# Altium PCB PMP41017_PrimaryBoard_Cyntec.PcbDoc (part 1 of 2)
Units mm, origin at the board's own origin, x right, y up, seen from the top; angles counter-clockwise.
Board outline 81.79 x 50.02 mm, 4 copper layers (Top Layer, Layer 2, Layer 3, Bottom Layer), stack 1.194 mm thick; 52 components, 42 nets, 218 pads, 652 vias.
Unrouted connection lines stored in the file: 2.
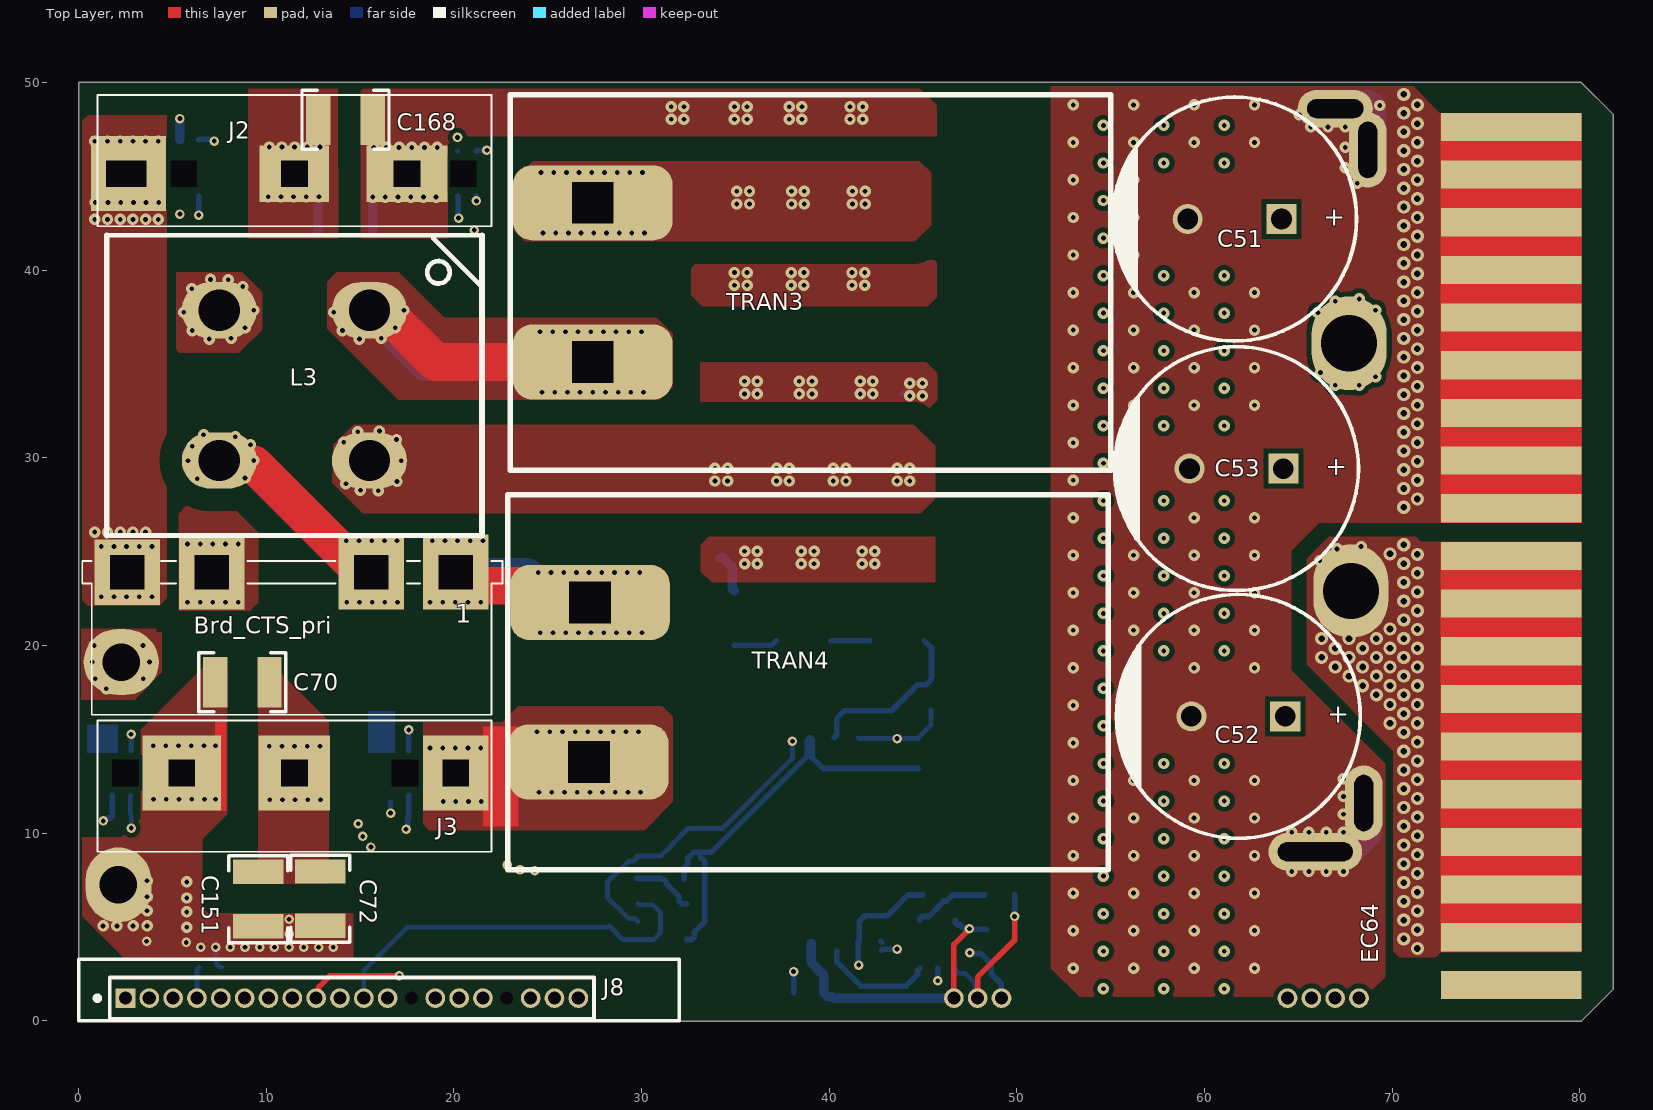
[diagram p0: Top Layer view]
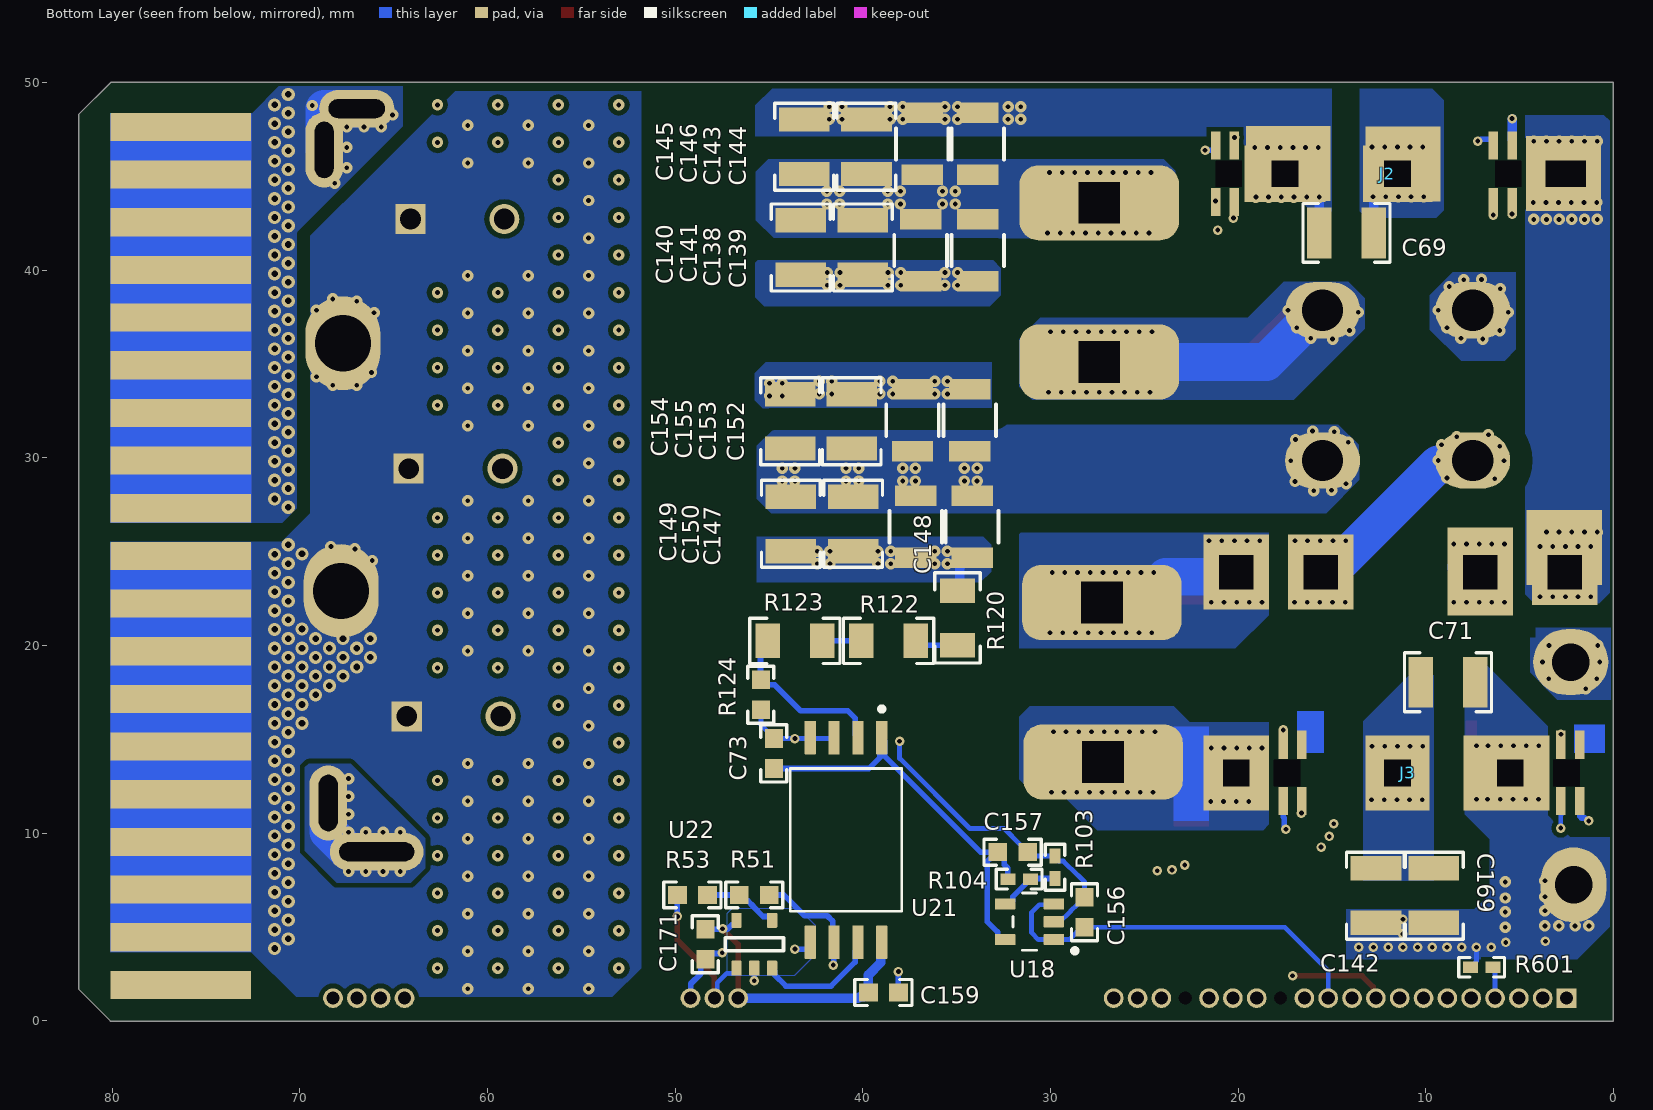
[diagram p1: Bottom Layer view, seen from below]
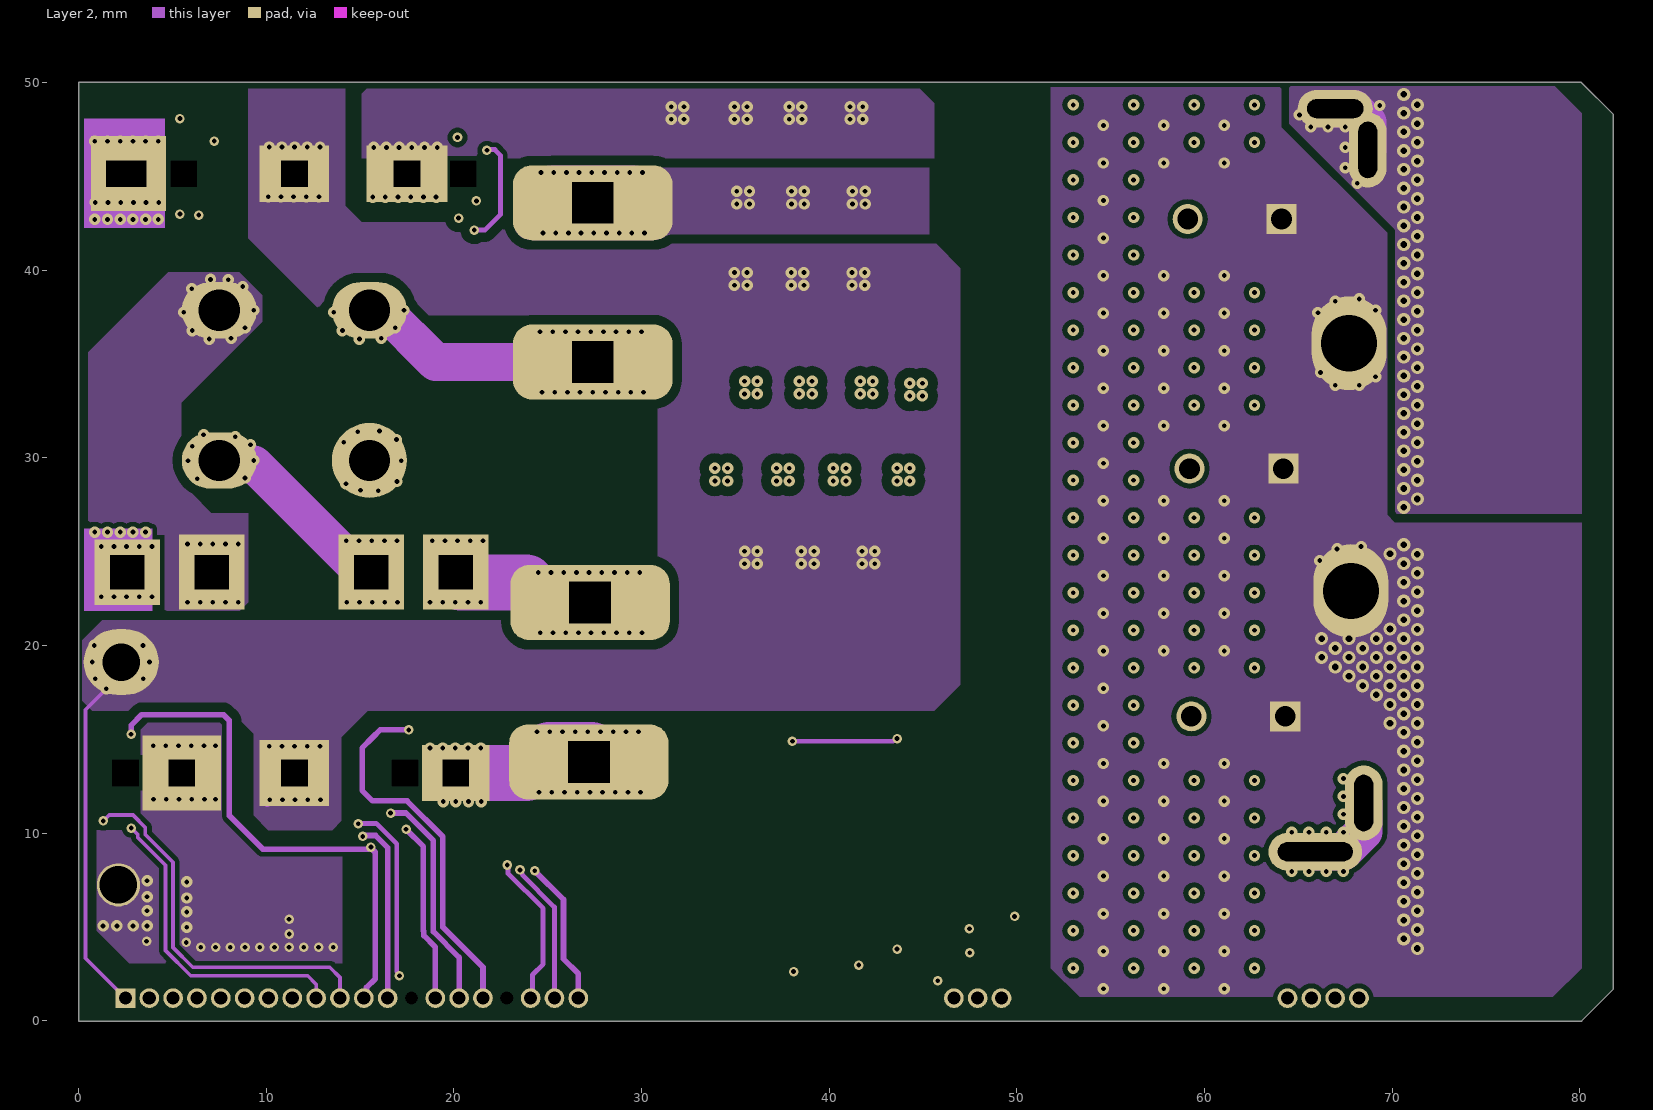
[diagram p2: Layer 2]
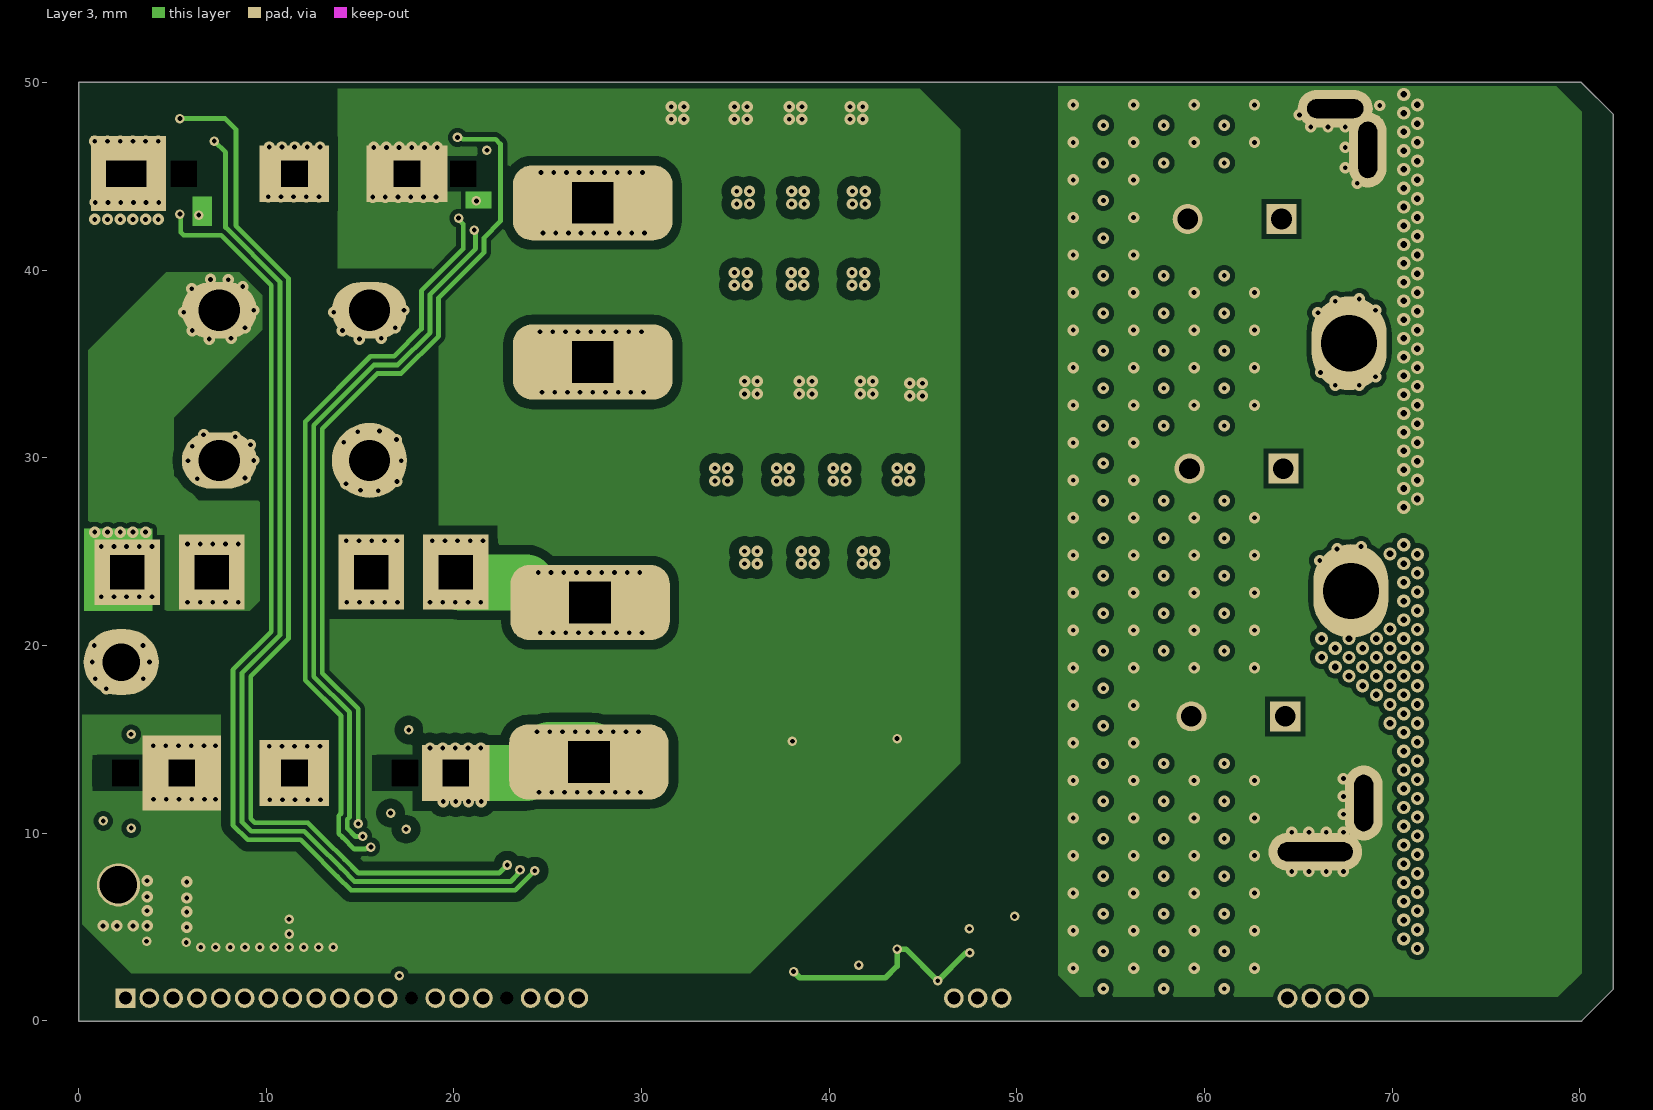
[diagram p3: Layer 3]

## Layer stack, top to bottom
Top Solder: solder mask 0.0102, Solder Resist, Dk 3.5
Top Layer: signal copper 0.07
Dielectric 1: prepreg 0.3048, PP-022, Dk 4.5
Layer 2: signal copper 0.07
Dielectric3: core 0.3048, Core-029, Dk 4.7
Layer 3: signal copper 0.07
Dielectric 5: prepreg 0.3048, PP-022, Dk 4.5
Bottom Layer: signal copper 0.07
Bottom Solder: solder mask 0.0102, Solder Resist, Dk 3.5

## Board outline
0,-0.017 0,50 70,50 80.071,50 81.788,48.283 81.788,1.683 80.088,-0.017

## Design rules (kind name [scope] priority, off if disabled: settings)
AcuteAngle [All] p1: minimum=4.50000000000000E+0001 checktracksonly=FALSE
AssemblyTestPointUsage [All] p1: valid=2
BoardOutlineClearance BoardOutlineClearance_MountingHoles [OnCopper and InComponentClass('Mounting Holes')] p1: gap=0.2 ignorepadtopadclearanceinfootprint=FALSE
BoardOutlineClearance BoardOutlineClearance_Poly [OnCopper and IsPoly] p2: gap=0.2 ignorepadtopadclearanceinfootprint=FALSE
BoardOutlineClearance [OnCopper and Not InComponentClass('Logo') and not InComponentClass('FiducialMark') and not InRegion(1000,500,4000,800) and not InPoly] p3: gap=0.2 ignorepadtopadclearanceinfootprint=FALSE
Clearance Clearance_HV [InNetClass('HV') And ( OnLayer('Top Layer') OR OnLayer('Bottom Layer')) vs InNetClass('All Nets')] p1: gap=1.2 ignorepadtopadclearanceinfootprint=TRUE
Clearance Clearance_HV_Mid [InNetClass('HV') And (OnMid OR OnMultiLayer) vs InNetClass('All Nets')] p2: gap=0.5 ignorepadtopadclearanceinfootprint=TRUE
Clearance Clearance_SW1P [InNetClass('SW1P') And ( OnLayer('Top Layer') OR OnLayer('Bottom Layer')) vs NOT InNetClass('SW1P')] p3: gap=1.2 ignorepadtopadclearanceinfootprint=TRUE
Clearance Clearance_SW1N [InNetClass('SW1N') And ( OnLayer('Top Layer') OR OnLayer('Bottom Layer')) vs NOT InNetClass('SW1N')] p4: gap=1.2 ignorepadtopadclearanceinfootprint=TRUE
Clearance Clearance_SW1N_Mid [InNetClass('SW1N') And ( OnMid OR OnMultiLayer) vs NOT InNetClass('SW1N')] p5: gap=0.5 ignorepadtopadclearanceinfootprint=TRUE
Clearance Clearance_SW2N_Mid [InNetClass('SW2N') And ( OnMid OR OnMultiLayer) vs NOT InNetClass('SW2N')] p6: gap=0.5 ignorepadtopadclearanceinfootprint=TRUE
Clearance Clearance_SW1P_Mid [InNetClass('SW1P') And ( OnMid OR OnMultiLayer) vs NOT InNetClass('SW1P')] p7: gap=0.5 ignorepadtopadclearanceinfootprint=TRUE
Clearance Clearance_SW2P_Mid [InNetClass('SW2P') And ( OnMid OR OnMultiLayer) vs NOT InNetClass('SW2p')] p8: gap=0.5 ignorepadtopadclearanceinfootprint=TRUE
Clearance Clearance_SW2P [InNetClass('SW2P') And ( OnLayer('Top Layer') OR OnLayer('Bottom Layer')) vs NOT InNetClass('SW2P')] p9: gap=1.2 ignorepadtopadclearanceinfootprint=TRUE
Clearance Clearance_SW2N [InNetClass('SW2N') And ( OnLayer('Top Layer') OR OnLayer('Bottom Layer')) vs NOT InNetClass('SW2N')] p10: gap=1.2 ignorepadtopadclearanceinfootprint=TRUE
Clearance Clearance_Keepouts [((IsTrack Or IsArc) And Not InPoly) And IsFree and IsKeepOut vs ((IsTrack Or IsArc) And Not InPoly) And IsFree and IsKeepOut] p11: gap=0 ignorepadtopadclearanceinfootprint=FALSE
Clearance Clearance_Poly [InPolygon] p12: gap=0.254 ignorepadtopadclearanceinfootprint=TRUE
Clearance Clearance_FiducialMark [IsKeepOut and InComponentClass('FiducialMark') vs IsPad and InComponentClass('FiducialMark')] p13: gap=0 ignorepadtopadclearanceinfootprint=FALSE
Clearance [All] p14: gap=0.203 ignorepadtopadclearanceinfootprint=TRUE
ComponentClearance ComponentClearance_MountingHoles_FiducialMarks [InComponentClass('Mounting Holes') vs InComponentClass('FiducialMark')] p1 off: gap=1.27 collisioncheckmode=3 verticalgap=0.254 showdistances=FALSE
ComponentClearance ComponentClearance_Shunt [InComponentClass('Header') vs InComponentClass('Shunt')] p2 off: gap=0 collisioncheckmode=3 verticalgap=0 showdistances=FALSE
ComponentClearance ComponentClearance_Logo [InComponentClass('Logo')] p3 off: gap=0.762 collisioncheckmode=3 verticalgap=0.254 showdistances=FALSE
ComponentClearance ComponentClearance_ScrewToNut [(HasFootprint('NY PMS 440 0025 PH')) vs (HasFootprint('Keystone_1902C'))] p4 off: gap=0.127 collisioncheckmode=3 verticalgap=0.254 showdistances=FALSE
ComponentClearance ComponentClearance_MountingHoles [InComponentClass('Mounting Holes')] p5 off: gap=2.54 collisioncheckmode=3 verticalgap=2540 showdistances=FALSE
ComponentClearance ComponentClearance_SmallPassives [HasFootprint('0201*') or HasFootprint('0402*') or HasFootprint('0508') or HasFootprint('0603*') or HasFootprint('0612') or HasFootprint('0805*') or HasFootprint('0815*') or HasFootprint('0830*') or HasFootprint('1206*') or HasFootprint('1210*') or HasFootprint('1808*') or HasFootprint('1812*') or HasFootprint('1825*') or HasFootprint('2010*') or HasFootprint('2220*') or HasFootprint('2225*') or HasFootprint('2512*') or HasFootprint('2728*') or HasFootprint('3518*') vs HasFootprint('0201*') or HasFootprint('0402*') or HasFootprint('0508') or HasFootprint('0603*') or HasFootprint('0612') or HasFootprint('0805*') or HasFootprint('0815*') or HasFootprint('0830*') or HasFootprint('1206*') or HasFootprint('1210*') or HasFootprint('1808*') or HasFootprint('1812*') or HasFootprint('1825*') or HasFootprint('2010*') or HasFootprint('2220*') or HasFootprint('2225*') or HasFootprint('2512*') or HasFootprint('2728*') or HasFootprint('3518*')] p6 off: gap=0.38 collisioncheckmode=3 verticalgap=0.254 showdistances=FALSE
ComponentClearance ComponentClearance_THtoSMT [IsThruComponent vs IsSMTComponent] p7 off: gap=0.762 collisioncheckmode=3 verticalgap=0.762 showdistances=FALSE
ComponentClearance ComponentClearance_THtoTH [IsThruComponent vs IsThruComponent] p8 off: gap=0.508 collisioncheckmode=3 verticalgap=0.762 showdistances=FALSE
ComponentClearance [All] p9 off: gap=0.508 collisioncheckmode=3 verticalgap=0.254 showdistances=FALSE
DiffPairsRouting [All] p1: maxlimit=2.54 minlimit=0.254 mostfreqgap=0.254 toplayer_minwidth=0.381 toplayer_maxwidth=0.381 toplayer_prefwidth=0.381 midlayer1_minwidth=0.381 midlayer1_maxwidth=0.381 midlayer1_prefwidth=0.381 midlayer2_minwidth=0.381 midlayer2_maxwidth=0.381 midlayer2_prefwidth=0.381 bottomlayer_minwidth=0.381 bottomlayer_maxwidth=0.381 bottomlayer_prefwidth=0.381 maxuncoupledlength=25.4
FabricationTestPointUsage TestPointUsage [All] p1: valid=2 allowmultiple=FALSE
FabricationTestpoint Testpoint [All] p1: side=3 testpointundercomponent=TRUE minsize=1.016 maxsize=2.54 preferedsize=1.524 minholesize=0 maxholesize=1.016 preferedholesize=0.813 testpointgrid=0.025 allowsidetop=TRUE allowsidebottom=TRUE usegrid=TRUE gridtolerance=0
FanoutControl Fanout_LCC [IsLCC] p1: bgadir=Out bgaviamode=Centered fanoutstyle=Auto fanoutdirection=Alternating viagrid=0.025 // Fanout_LCC (Default Rule)
FanoutControl Fanout_BGA [IsBGA] p2: bgadir=Out bgaviamode=Centered fanoutstyle=Auto fanoutdirection=Alternating viagrid=0.025 // Fanout_BGA (Default Rule)
FanoutControl Fanout_Default [All] p4: bgadir=Out bgaviamode=Centered fanoutstyle=Auto fanoutdirection=Alternating viagrid=0.025 // Fanout_Default (Default Rule)
FanoutControl Fanout_Small [(CompPinCount < 5)] p5: bgadir=Out bgaviamode=Centered fanoutstyle=Auto fanoutdirection=OutThenIn viagrid=0.025 // Fanout_Small (Default Rule)
Height [All] p1 off: minheight=0 maxheight=30 prefheight=12.7
HoleSize [All] p1: absolutevalues=TRUE maxlimit=6.375 minlimit=0.178 maxpercent=80.000 minpercent=20.000
MinimumAnnularRing MinimumAnnularRing_ThermalPadVias [IsVia and InAnyComponent] p1: minimumring=0.15
MinimumAnnularRing [All] p2: minimumring=0.12
MinimumSolderMaskSliver MinimumSolderMaskSliver_Logo [InComponentClass('Logo') vs InComponentClass('Logo')] p1: minsoldermaskwidth=0.018
MinimumSolderMaskSliver [All] p2: minsoldermaskwidth=0.1
PlaneConnect [All] p1: planeconnectstyle=Relief reliefexpansion=0.254 reliefentries=4 reliefconductorwidth=0.254 reliefairgap=0.254
PolygonConnect [All] p1: connectstyle=Direct reliefconductorwidth=0.254 reliefentries=4 polygonreliefangle="90 Angle" airgapwidth=0.254
RoutingVias ThermalPadVias [IsVia and InAnyComponent] p1: holewidth=0.2 width=0.5 viastyle="Through Hole" minholewidth=0.2 minwidth=0.5 maxholewidth=0.33 maxwidth=0.6
RoutingVias [All] p2: holewidth=0.3 width=0.5 viastyle="Through Hole" minholewidth=0.2 minwidth=0.5 maxholewidth=1.016 maxwidth=1.651
SilkToBoardRegionClearance [Not ((IsComment or IsDesignator) And (Hide <> 'False')) and not InRegion(1000,500,4000,800)] p1:
SilkToSilkClearance SilkToSilkClearance_Pb-FreeLogo [(HasFootprint('Pb-Free_Overlay_Medium') OR HasFootprint('Pb-Free_Overlay_Small')) vs (HasFootprint('Pb-Free_Overlay_Medium') OR HasFootprint('Pb-Free_Overlay_Small'))] p1: silktosilkclearance=0
SilkToSilkClearance [All] p2: silktosilkclearance=0.1
SilkToSolderMaskClearance SilkToComponentPadClearance [(IsPad or IsFill or IsRegion) and InAnycomponent] p1: minsilkscreentomaskgap=0.127 clearancetoexposedcopper=TRUE
SilkToSolderMaskClearance "Silk to Solder Mask Opening" [All] p2: minsilkscreentomaskgap=0.1 clearancetoexposedcopper=FALSE
SolderMaskExpansion [All] p1: expansion=0.05 istentingtop=FALSE
UnRoutedNet [All] p1: checkbadconnections=TRUE
Width [All] p1: maxlimit=5 minlimit=0.152 preferedwidth=0.254 checkconnectedcopper=TRUE
13 further rules are at their usual default settings.

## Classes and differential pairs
net class SW2P: GaN2_12V_H GaN2_INH GaN2_SW GaN2_SW_D TEMP_2H_1
net class SW2N: CT2_N CT2_P NetC147_2
net class SW1P: CT1_N CT1_P GaN1_12V_H GaN1_INH GAN1_SW1_D TEMP_1H_1 TR1_HV_P
net class SW1N: TR1_HV_N
net class HV: HVBUS

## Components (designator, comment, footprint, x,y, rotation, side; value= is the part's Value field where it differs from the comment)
Brd_CTS_pri "CTS daughter board" DB_PMP41017_CST 22.6,23.9 r180 top locked
C51 "860020378023" 860020378023 61.6,42.717 r180 top value=3300uF
C52 "860020378023" 860020378023 61.8,16.217 r180 top value=3300uF
C53 "860020378023" 860020378023 61.7,29.417 r180 top value=3300uF
C69 "CGA6L1X7T2J104K160AC" 1210_200 14.224,41.977 r0 bottom value=0.1uF
C70 "CGA6L1X7T2J104K160AC" 1210_200 8.724,18.034 r180 top value=0.1uF
C71 "CGA6L1X7T2J104K160AC" 1210_200 8.818,18.034 r180 bottom value=0.1uF
C72 "CGA6L1X7T2J104K160AC" 1210_200 12.88,6.5 r270 top value=0.1uF
C73 "GCM188R71E104KA57D" 0603 44.737,14.241 r90 bottom value=0.1uF
C138 "C3225C0G2J333J250AA" 1210_280 36.918,41.046 r90 bottom value=0.033uF
C139 "C3225C0G2J333J250AA" 1210_280 33.87,41.046 r90 bottom value=0.033uF
C140 "CGA6N4NP02J223J230AA" 1210_250 43.307,41.202 r90 bottom value=0.022uF
C141 "CGA6J4C0G2J103J125AA" 1210_150 39.994,41.202 r90 bottom value=0.01uF
C142 "CGA6L1X7T2J104K160AC" 1210_200 12.652,6.664 r270 bottom value=0.1uF
C143 "C3225C0G2J333J250AA" 1210_280 36.83,46.724 r90 bottom value=0.033uF
C144 "C3225C0G2J333J250AA" 1210_280 33.87,46.724 r90 bottom value=0.033uF
C145 "CGA6N4NP02J223J230AA" 1210_250 43.119,46.568 r90 bottom value=0.022uF
C146 "CGA6J4C0G2J103J125AA" 1210_150 39.805,46.568 r90 bottom value=0.01uF
C147 "C3225C0G2J333J250AA" 1210_280 37.173,26.32 r90 bottom value=0.033uF
C148 "C3225C0G2J333J250AA" 1210_280 34.173,26.32 r90 bottom value=0.033uF
C149 "CGA6N4NP02J223J230AA" 1210_250 43.83,26.475 r90 bottom value=0.022uF
C150 "CGA6J4C0G2J103J125AA" 1210_150 40.516,26.475 r90 bottom value=0.01uF
C151 "CGA6L1X7T2J104K160AC" 1210_200 9.578,6.477 r270 top value=0.1uF
C152 "C3225C0G2J333J250AA" 1210_280 34.304,31.996 r90 bottom value=0.033uF
C153 "C3225C0G2J333J250AA" 1210_280 37.354,31.996 r90 bottom value=0.033uF
C154 "CGA6N4NP02J223J230AA" 1210_250 43.873,31.941 r90 bottom value=0.022uF
C155 "CGA6J4C0G2J103J125AA" 1210_150 40.595,31.941 r90 bottom value=0.01uF
C156 "C1608X7R1E104K080AA" 0603 28.183,5.778 r90 bottom value=0.1uF
C157 "C1608X7R1E104K080AA" 0603 32.014,8.981 r180 bottom value=0.1uF
C159 "GCM188R71E104KA57D" 0603 38.901,1.501 r180 bottom value=0.1uF
C168 "CGA6L1X7T2J104K160AC" 1210_200 14.224,48.006 r0 top value=0.1uF
C169 "CGA6L1X7T2J104K160AC" 1210_200 9.578,6.664 r270 bottom value=0.1uF
C171 "GCM188R71E104KA57D" 0603 48.387,4.074 r270 bottom value=0.1uF
EC64 "EDGE_CONN_PCIe-x4" EC_10035388-102LF 81.788,47.625 r90 top
J2 "GaN Borad" ?#1 22,49.333 r180 top
J3 "GaN Borad" ?#2 1,9 r0 top
J8 "M52-5002045" M52-5002045 2.5,1.2 r0 top locked
L3 "PQ2016" "CHOKE-PQ2016 - H" 11.5,33.852 r180 top
R51 "RC0603FR-0712KL" 0603 45.781,6.701 r180 bottom value=12.0k
R53 "RC0603FR-0712KL" 0603 49.078,6.701 r180 bottom value=12.0k
R103 "" 0402 29.759,8.176 r270 bottom value=1.18Meg
R104 "" 0402 31.673,7.541 r0 bottom value=1.96Meg
R120 "CRCW12061M00FKEA" 1206 34.948,21.461 r90 bottom value=1.00Meg
R122 "CRCW12061M00FKEA" 1206 38.623,20.241 r180 bottom value=1.00Meg
R123 "CRCW12061M00FKEA" 1206 43.616,20.241 r180 bottom value=1.00Meg
R124 "RC0603FR-0712KL" 0603 45.429,17.37 r90 bottom value=12.0k
R601 "" 0402 7.024,2.846 r180 bottom value=0
TRAN3 "PQ32" PQ3220-1500-400V12V_pri#1 39.005,39.333 r0 top locked
TRAN4 "PQ32" PQ3220-1500-400V12V_pri#2 38.862,18.034 r0 top
U18 "TPS7A2401DBVR" DBV0005A-MFG 31.115,5.274 r0 bottom
U21 "AMC1311BQDWVRQ1" DWV0008A-MFG 40.894,9.632 r270 bottom
U22 "TS321IDBVR" DBV0005A_L 45.781,4.074 r90 bottom

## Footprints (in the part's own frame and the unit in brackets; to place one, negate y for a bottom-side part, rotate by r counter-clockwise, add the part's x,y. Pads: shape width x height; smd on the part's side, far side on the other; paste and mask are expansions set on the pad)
0402 [mm] "0402 from SM-752 data"
  rect 0.8x0.6 smd: 1(-0.6,0) 2(0.6,0)
  silkscreen extent -1.22,-0.52 1.22,0.52, body extent -0.55,-0.3 0.55,0.3, height 0.6
0603 [mm] "0603 from SM-752 data"
  rect 1x0.95 smd: 1(-0.8,0) 2(0.8,0)
  silkscreen extent -1.52,-0.69 1.52,0.69, body extent -0.87,-0.47 0.87,0.47, height 1
1206 [mm] "1206 from SM-752 data"
  rect 1.3x1.85 smd: 1(-1.45,0) 2(1.45,0)
  silkscreen extent -2.4,-1.21 2.4,1.21, body extent -1.7,-0.9 1.7,0.9, height 1.35
1210_150 [mm] "1210"
  rect 1.3x2.7 smd: 1(-1.45,0) 2(1.45,0)
  silkscreen extent -2.32,-1.57 2.32,1.57, body extent -1.7,-1.35 1.7,1.35, height 1.5
1210_200 [mm] "1210"
  rect 1.3x2.7 smd: 1(-1.45,0) 2(1.45,0)
  silkscreen extent -2.32,-1.57 2.32,1.57, body extent -1.7,-1.35 1.7,1.35, height 2
1210_250 [mm] "1210"
  rect 1.3x2.7 smd: 1(-1.45,0) 2(1.45,0)
  silkscreen extent -2.32,-1.57 2.32,1.57, body extent -1.7,-1.35 1.7,1.35, height 2.5
1210_280 [mm] "SMD, 2-Leads, Body 3.6x2.8mm, Height 2.8mm"
  rect 1.1x2.2 smd: 1(-1.65,0) 2(1.65,0)
  silkscreen extent -0.84,-1.4 0.84,1.4, body extent -1.8,-1.4 1.8,1.4, height 2.8
860020378023 [mm] "TH, 2-Leads, Dia 13mm, Lead Spacing 5mm"
  rect 1.6x1.6 hole 1.1: 1(-2.5,0)
  round 1.6 hole 1.1: 2(2.5,0)
  silkscreen extent -6.5,-6.5 6.55,6.5, body extent -8.25,-8.25 8.26,8.25, height 33.51
"CHOKE-PQ2016 - H" [mm]
  oval 4x3 hole 2.2: 1(-4,-4) 2(4,-4) 3(4,4)
  oval 4x3 / inner round 4 / far side oval 4x3 hole 2.2: 4(-4,4)
  silkscreen extent -10,-8 10,8
DB_PMP41017_CST [mm]
  rect 3.5x4 hole 1.8 square: 1(2.5,0) 2(7,0) 3(15.5,0)
  rect 3.5x3.5 hole 1.8 square: 4(20,0)
  silkscreen extent 0,-0.6 22.4,7.6
DBV0005A-MFG [mm]
  rrect17% 1.1x0.6 smd paste+0 mask+0: 1(-1.3,0.95) 2(-1.3,0) 3(-1.3,-0.95) 4(1.3,-0.95) 5(1.3,0.95)
  silkscreen extent -2.54,-1.53 0.87,1.67, body extent -1.4,-1.45 1.4,1.45, height 1.45
DBV0005A_L [mm] "SOT23, 5-Leads, Body 2.9x1.6mm, Pitch 0.95mm, Lead Span 2.8mm, IPC High Density"
  rrect18% 0.8x0.55 smd: 1(-1.275,0.95) 2(-1.275,0) 3(-1.275,-0.95) 4(1.275,-0.95) 5(1.275,0.95)
  silkscreen extent -0.35,-1.55 0.35,1.55, body extent -1.42,-1.46 1.42,1.46, height 1.09
DWV0008A-MFG [mm]
  rrect17% 1.8x0.6 smd paste+0 mask+0: 1(-5.45,1.905) 2(-5.45,0.635) 3(-5.45,-0.635) 4(-5.45,-1.905) 5(5.45,-1.905) 6(5.45,-0.635) 7(5.45,0.635) 8(5.45,1.905)
  silkscreen extent -7.1,-2.98 3.8,2.98, body extent -5.75,-2.93 5.75,2.92, height 2.8
EC_10035388-102LF [mm] "Golden Finger"
  rect 1.5x7.5 smd: A1(0,5.45) A2(-2.54,5.45) A3(-5.08,5.45) A4(-7.62,5.45) A5(-10.16,5.45) A6(-12.7,5.45) A7(-15.24,5.45) A8(-17.78,5.45) A9(-20.32,5.45) A10(-22.86,5.45) A11(-25.4,5.45) A12(-27.94,5.45) A13(-30.48,5.45) A14(-33.02,5.45) A15(-35.56,5.45) A16(-38.1,5.45) A17(-40.64,5.45) A18(-43.18,5.45) A19(-45.72,5.45)
  rect 1.5x7.5 smd far side: B1(0,5.45) B2(-2.54,5.45) B3(-5.08,5.45) B4(-7.62,5.45) B5(-10.16,5.45) B6(-12.7,5.45) B7(-15.24,5.45) B8(-17.78,5.45) B9(-20.32,5.45) B10(-22.86,5.45) B11(-25.4,5.45) B12(-27.94,5.45) B13(-30.48,5.45) B14(-33.02,5.45) B15(-35.56,5.45) B16(-38.1,5.45) B17(-40.64,5.45) B18(-43.18,5.45) B19(-45.72,5.45)
M52-5002045 [mm] "CONN RCPT 20POS 0.05 GOLD PCB"
  rect 1.05x1.05 hole 0.7: 1(0,0)
  round 1.05 hole 0.7: 2(1.27,0) 3(2.54,0) 4(3.81,0) 5(5.08,0) 6(6.35,0) 7(7.62,0) 8(8.89,0) 9(10.16,0) 10(11.43,0) 11(12.7,0) 12(13.97,0) 14(16.51,0) 15(17.78,0) 16(19.05,0) 18(21.59,0) 19(22.86,0) 20(24.13,0)
  round 0 hole 0.7 unplated: 13(15.24,0) 17(20.32,0)
  silkscreen extent -1.6,-1.1 24.97,1.1, body extent -0.84,-1.1 24.97,1.1, height 4.1
PQ3220-1500-400V12V_pri#1 [mm] "1500W Transformer from 400V to 12V with PQ3220 Core"
  rrect50% 8.5x4 hole 2.2 square: 1(-11.605,-4.234) 2(-11.605,4.246)
  silkscreen extent -16,-10 16,10
PQ3220-1500-400V12V_pri#2 [mm] "1500W Transformer from 400V to 12V with PQ3220 Core"
  rrect50% 8.5x4 hole 2.2 square: 1(-11.67,-4.245) 2(-11.604,4.244)
  silkscreen extent -16,-10 16,10
?#1 [mm]
  round 0 hole 1.4 square unplated: 0(16.4,4.2) 4(1.5,4.2)
  rect 0.5x1.5 smd far side: 1(0.8,5.7) 2(0.8,2.7) 3(1.8,5.7) 4(1.8,2.7) 5(15.6,5.7) 6(15.6,2.7) 7(16.6,5.7) 8(16.6,2.7)
  rect 3.7x3 hole 1.4 square: HV(10.5,4.2)
  rect 4.3x3 hole 1.4 square: PG(4.5,4.2)
  rect 3.5x4 hole 1.4 square: SW(19.1,4.2)
  silkscreen extent 0,0 21,7
?#2 [mm]
  round 0 hole 1.4 square unplated: 0(16.4,4.2) 4(1.5,4.2)
  rect 0.5x1.5 smd far side: 1(0.8,5.7) 2(0.8,2.7) 3(1.8,5.7) 4(1.8,2.7) 5(15.6,5.7) 6(15.6,2.7) 7(16.6,5.7) 8(16.6,2.7)
  rect 3.8x4 / inner rect 3.7x3.5 / far side rect 3.4x4 hole 1.4 square: HV(10.5,4.2)
  rect 4.2x4 hole 1.4 square: PG(4.5,4.2)
  rect 3.5x4 / inner rect 3.6x3 / far side rect 3.5x4 hole 1.4 square: SW(19.1,4.2)
  silkscreen extent 0,0 21,7

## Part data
Brd_CTS_pri: library part Board_CTS
C51 C52 C53: library part Cap_Polarized_1, "CAP, AL, 3300 uF, 16 V, +/- 20%, 0.023 ohm, TH", Cap_Case=13x25mm, Manufacturer="Würth Elektronik", Supplier Part Number 1=710-860020378023, Tolerance_%=20%, Value1="0.034 ohm", Value2=16V, ValueDisplayed=3300uF
C69 C70 C71 C72 C142 C151 C168 C169: library part CMP-0009140-2, "CAP, CERM, 0.1 uF, 630 V, +/- 10%, X7R, AEC-Q200 Grade 1, 1210", Cap_Case=1210, Manufacturer=TDK, Supplier Part Number 1=445-7116-1-ND, TempCo=X7R, Tolerance_%=10%, Value1=Unknown, Value2=630V, ValueDisplayed=0.1uF
C73 C159 C171: library part CMP-0084679-1, "CAP, CERM, 0.1 µF, 25 V,+/- 10%, X7R, AEC-Q200 Grade 1, 0603", Cap_Case=0603, Manufacturer=MuRata, TempCo=X7R, Tolerance_%=10%, Value2=25V, ValueDisplayed=0.1µF
C138 C139 C143 C144 C147 C148 C152 C153: library part CMP-0009097-2, "CAP, CERM, 0.033 uF, 630 V, +/- 5%, C0G/NP0, 1210", Cap_Case=1210, Manufacturer=TDK, Supplier Part Number 1=445-14880-1-ND, TempCo=C0G/NP0, Tolerance_%=5%, Value1=Unknown, Value2=630V, ValueDisplayed=0.033uF
C140 C145 C149 C154: library part CMP-0009153-2, "CAP, CERM, 0.022 uF, 630 V, +/- 5%, C0G/NP0, AEC-Q200 Grade 0,", Cap_Case=1210, Manufacturer=TDK, Supplier Part Number 1=445-172570-1-ND, TempCo=C0G/NP0, Tolerance_%=5%, Value1=Unknown, Value2=630V, ValueDisplayed=0.022uF
C141 C146 C150 C155: library part CMP-0860380-1, "CAP, CERM, 0.01 µF, 630 V,+/- 5%, C0G/NP0, AEC-Q200 Grade 1, 1210", Cap_Case=1210, Manufacturer=TDK, TempCo=C0G/NP0, Tolerance_%=5%, Value2=630V, ValueDisplayed=0.01µF
C156 C157: library part CMP-0007039-5, "CAP, CERM, 0.1 uF, 25 V, +/- 10%, X7R, 0603", Cap_Case=0603, Manufacturer=TDK, Supplier Part Number 1=445-1316-1-ND, TempCo=X7R, Tolerance_%=10%, Value1=Unknown, Value2=25V, ValueDisplayed=0.1uF
EC64: library part EDGE_CONN_CRPS, "Card Edge Footprint for CRPS Server PSU, 2.54mm, 25x2", Manufacturer="Texas Instruments", PartNumber=EDGE_CONN_PCI
J2 J3: library part Brd_GaN_footprint
J8: library part Receptacle_20x1, "Receptacle, 20x1, 1.27mm, TH", Manufacturer="Harwin Inc.", Supplier Part Number 1=952-1903-ND
L3: library part INDUCTOR_COUPLED, "Customized Resonant Choke", Manufacturer="YAXIN ELECTRONIC TECH", PartNumber=YXS50494T
R51 R53 R124: library part CMP-0022779-5, "RES, 12.0 k, 1%, 0.1 W, 0603", Manufacturer=Yageo, Power_W=100mW, Supplier Part Number 1=311-12.0KHRCT-ND, TempCo="100 ppm/C", Tolerance_%=1%, Value2=0.1W, Value_Code=12k0, ValueDisplayed=12.0k
R103: library part Res1, "RES, 1.18Meg, 1%, 0.1 W, 0402"
R104: library part Res1, "RES, 1.96Meg, 1%, 0.1 W, 0402"
R120 R122 R123: library part CMP-0016716-3, "RES, 1.00 M, 1%, 0.25 W, AEC-Q200 Grade 0, 1206", Manufacturer=Vishay-Dale, Power_W=250mW, Supplier Part Number 1=541-1.00MFCT-ND, TempCo="100 ppm/C", Tolerance_%=1%, Value2=0.25W, Value_Code=1M00, ValueDisplayed=1.00M
R601: library part Res1, "RES, 0, 5%, 0.1 W, AEC-Q200 Grade 0, 0402"
TRAN3 TRAN4: library part Transformer_pri, "PQ32 TRANSFORMER", Manufacturer="YAXIN ELECTRONIC TECH"
U18: library part CMP-0089843-1, "Linear Voltage Regulator IC 1 Output 200mA SOT-23-5", Digikey Part Number=296-TPS7A2401DBVRCT-ND, Dropout Voltage=160mV, Manufacturer="Texas Instruments", Max Supply Voltage=18V, Min Supply Voltage=2.4V, Mouser Part Number=595-TPS7A2401DBVR, Nominal Supply Current=2uA, Operating Temperature Range="-40°C to +125°C", Output Voltage=1.24-17.75V
U21: library part CMP-0090465-1, "Automotive 2-V input, reinforced isolated amplifier with high CMTI for voltage sensing 8-SOIC -40 to 125", Digikey Part Number=296-50938-1-ND, Input Bias Current=0.0035uA, Input Offset Voltage=-1.1mV, Manufacturer="Texas Instruments", Max Supply Voltage=5.5V, Min Supply Voltage=3V, Mouser Part Number=595-AMC1311BQDWVRQ1, Nominal Supply Current=5.3-7.1mA, Operating Temperature Range="-40°C to +125°C", Output Current Per Channel=13mA
U22: library part CMP-0043733-1, "Low-Power Single Operational Amplifier, 3 to 30 V, -40 to 125 degC, 5-pin SOT23 (DBV5), Green (RoHS & no Sb/Br)", Manufacturer="Texas Instruments", Total Supply Voltage(Max)(+5V is 5, +/-5V is 10)=30, Total Supply Voltage(Min)(+5V is 5, +/-5V is 10)=3

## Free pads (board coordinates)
  oval 5x2 hole 1 slot 4 at 0 deg: 4(65.9,9)
  oval 4x2 hole 1 slot 3 at 0 deg: 4(66.963,48.6)
  oval 4x5 hole 3: 4(67.7,36.1) 5(67.8,22.9)
  oval 2x4 hole 1 slot 3 at 90 deg: 4(68.481,11.6) 4(68.7,46.4)
  oval 3.5x4 / inner round 2.3 / far side oval 3.5x4 hole 2: 5(2.126,7.238)
  rect 3x4 hole 1.4 square: 5(2.171,45.133)
  oval 4x3.5 hole 2: 5(2.276,19.11)
  rect 4x4 smd far side: 5(2.623,25.218) 5(11.206,45.654)
  rect 2x4 smd far side: 5(6.985,13.2)
  rect 4.5x4 smd far side: 5(17.321,45.681)
  round 1.05 hole 0.7: 5(46.64,1.2) 5(47.91,1.2) 5(49.18,1.2) 5(64.42,1.2) 5(65.69,1.2) 5(66.96,1.2) 5(68.23,1.2)
  rect 3.5x2 smd far side: 6(7.1,25.273) 7(7.1,22.595)

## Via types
v1: diameter 0.61, hole 0.254, Top Layer to Bottom Layer, tented both sides, 497 vias
v2: diameter 0.7, hole 0.35, Top Layer to Bottom Layer, tented both sides, 110 vias
v3: diameter 0.508, hole 0.254, Top Layer to Bottom Layer, tented both sides, 45 vias

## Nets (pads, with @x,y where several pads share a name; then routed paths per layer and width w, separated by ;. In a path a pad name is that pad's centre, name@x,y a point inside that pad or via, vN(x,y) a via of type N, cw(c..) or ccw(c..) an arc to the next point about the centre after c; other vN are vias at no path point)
3V3p_1: C73.1 C157.1 R104.2 U18.5 U21.1 | length 23.2
  Bottom Layer w0.3: R104.2@32.273,7.541 32.273,8.127 32.465,8.319 32.465,8.656 32.79,8.981 C157.1@32.814,8.981 C157.1@33.127,8.981 ; U18.5@32.415,4.324 32.665,4.324 32.815,4.474 32.815,4.724 33.371,5.28 33.371,8.48 33.195,8.656 33.164,8.656 33.127,8.693 C157.1@33.127,8.981 ; C73.1@44.737,13.441 39.672,13.441 39.085,14.028 39.085,14.987 U21.1@38.989,15.082 38.839,14.932 38.839,14.097 33.723,8.981 C157.1@33.127,8.981
12VL: C156.1 J2.3 J3.3 J8.11 U18.1 U18.3 | length 90.8
  Layer 2 w0.3: v3(2.8,15.258) 2.8,15.737 3.363,16.3 7.733,16.3 8.033,16 8.033,10.925 9.814,9.144 v3@15.405,9.144 ; J8.11@15.2,1.2 15.344,1.344 15.344,1.767 15.806,2.23 15.806,8.979 15.579,9.206 v3(15.579,9.254)
  Layer 3 w0.254: v3(15.579,9.254) 15.531,9.206 15.365,9.206 15.303,9.144 14.692,9.144 14.07,9.767 13.864,9.973 13.864,10.92 13.984,11.041 13.984,16.239 12.076,18.147 12.076,31.922 15.556,35.402 16.814,35.402 18.271,36.859 18.271,38.893 20.5,41.122 20.5,42.451 20.253,42.698 v3(20.253,42.767)
  Bottom Layer w0.254: J8.11@15.2,1.2 15.2,2.673 17.505,4.978 C156.1@28.183,4.978 ; C156.1@28.285,5.046 29.007,4.324 U18.1@29.815,4.324 30.643,4.324 31.008,4.689 31.008,5.768 30.597,6.179 29.859,6.179 U18.3@29.815,6.224
  Bottom Layer w0.3: J3.3@2.8,14.4 J3.3@2.8,15.246 ; J2.3@20.2,43.933 20.226,43.907 20.226,42.793 v3(20.253,42.767)
12Vout: C51.1 C52.1 C53.1 EC64.A10 EC64.A11 EC64.A12 EC64.A13 EC64.A14 EC64.A15 EC64.A16 EC64.A17 EC64.A18 EC64.B10 EC64.B11 EC64.B12 EC64.B13 EC64.B14 EC64.B15 EC64.B16 EC64.B17 EC64.B18 pad.4@67.7,36.1 pad.5@67.8,22.9 | length 10.5
  Top Layer w0.254: v1(66.178,34.543) 67.7,36.065 pad.4@67.7,36.1 ; pad.5@67.8,21.291 pad.5@67.8,22.9
  Top Layer w2: pad.4@67.7,36.1 pad.4@67.75,36.05 ; pad.5@67.75,22.95 pad.5@67.8,22.9
  Layer 3 w2: pad.4@67.7,36.1 pad.4@67.75,36.05 ; pad.5@67.75,22.95 pad.5@67.8,22.9
  Bottom Layer w0.254: 72.78,18.118 72.78,17.768 73.404,17.145 75.712,17.145 76.335,16.522 EC64.B14@76.335,14.563
  other v1: 54.61,1.705 57.83,1.705 61.05,1.705 54.61,3.705 57.83,3.705 61.05,3.705 54.61,5.705 57.83,5.705 61.05,5.705 54.61,7.705 57.83,7.705 61.05,7.705 54.61,9.705 57.83,9.705 61.05,9.705 54.61,11.705 57.83,11.705 61.05,11.705 54.61,13.705 57.83,13.705 61.05,13.705 54.61,15.705 54.61,17.705 54.61,19.705 57.83,19.705 61.05,19.705 54.61,21.705 57.83,21.705 61.05,21.705 54.61,23.705 57.83,23.705 61.05,23.705 66.14,24.519 67.063,25.137 68.342,25.263 54.61,25.705 57.83,25.705 61.05,25.705 54.61,27.705 57.83,27.705 61.05,27.705 54.61,29.705 54.61,31.705 57.83,31.705 61.05,31.705 54.61,33.705 57.83,33.705 61.05,33.705 66.963,33.865 68.242,33.865 69.113,34.308 54.61,35.705 57.83,35.705 61.05,35.705 54.61,37.705 57.83,37.705 61.05,37.705 66.04,37.719 69.113,37.858 66.963,38.337 68.242,38.463 54.61,39.705 57.83,39.705 61.05,39.705 54.61,41.705 54.61,43.705 54.61,45.705 57.83,45.705 61.05,45.705 54.61,47.705 57.83,47.705 61.05,47.705
  other v2: 71.341,3.847 70.612,4.359 71.341,4.847 70.612,5.359 71.341,5.847 70.612,6.359 71.341,6.847 70.612,7.359 71.341,7.847 70.612,8.359 71.341,8.847 70.612,9.359 71.341,9.847 70.612,10.359 71.341,10.847 70.612,11.359 71.341,11.847 70.612,12.359 71.341,12.847 70.612,13.359 71.341,13.847 70.612,14.359 71.341,14.847 70.612,15.359 69.883,15.847 71.341,15.847 70.612,16.359 69.883,16.847 71.341,16.847 69.154,17.359 70.612,17.359 68.425,17.847 69.883,17.847 71.341,17.847 67.696,18.359 69.154,18.359 70.612,18.359 66.966,18.847 68.425,18.847 69.883,18.847 71.341,18.847 66.237,19.359 67.696,19.359 69.154,19.359 70.612,19.359 66.966,19.847 68.425,19.847 69.883,19.847 71.341,19.847 66.237,20.359 67.696,20.359 69.154,20.359 70.612,20.359 71.341,20.847 69.883,20.87 70.612,21.359 71.341,21.847 70.612,22.359 71.341,22.847 70.612,23.359 71.341,23.847 70.612,24.359 71.341,24.847 69.883,24.87 70.612,25.359
CT1_N: Brd_CTS_pri.3 L3.2 pad.6 pad.7 | length 1.7
  Top Layer w2: Brd_CTS_pri.3@6.35,24.15 6.6,23.9 Brd_CTS_pri.3@7.1,23.9
  Bottom Layer w2: Brd_CTS_pri.3@7.1,23.9 7.35,24.15 Brd_CTS_pri.3@7.85,24.15
  other v1: 5.805,22.295 6.481,22.295 7.157,22.295 7.833,22.295 8.509,22.295 5.805,25.4 6.481,25.4 7.157,25.4 7.833,25.4 8.509,25.4 6.967,36.319 8.128,36.36 6.058,36.774 8.875,36.92 5.6,37.746 9.339,37.852 6.033,39.006 8.753,39.12 7.982,39.477 7.03,39.497
CT1_P: Brd_CTS_pri.4 J2.SW pad.5@2.171,45.133 pad.5@2.623,25.218 | length 0.6
  Bottom Layer w2: Brd_CTS_pri.4@2.1,24.15 2.35,23.9 Brd_CTS_pri.4@2.6,23.9
  other v1: 1.209,22.595 1.885,22.595 2.561,22.595 3.237,22.595 3.913,22.595 1.209,25.273 1.885,25.273 2.561,25.273 3.237,25.273 3.913,25.273 0.868,26.035 1.544,26.035 2.22,26.035 2.896,26.035 3.572,26.035 0.868,42.697 1.544,42.697 2.22,42.697 2.896,42.697 3.572,42.697 4.248,42.697 0.893,43.604 1.569,43.604 2.246,43.604 2.922,43.604 3.598,43.604 4.274,43.604 0.868,46.856 1.544,46.856 2.22,46.856 2.896,46.856 3.572,46.856 4.248,46.856
CT2_N: Brd_CTS_pri.2 L3.3 | length 38.2
  Top Layer w0.254: v1(5.825,29.834) 7.482,29.834 L3.3@7.5,29.852 7.5,30.265 v1(8.355,31.12)
  Top Layer w2: L3.3@7.5,29.852 7.691,29.661 9.339,29.661 14.85,24.15 15.35,24.15 Brd_CTS_pri.2@15.6,23.9
  Layer 2 w0.254: v1(6.058,30.604) 6.81,29.852 L3.3@7.5,29.852 ; v1(6.32,28.874) 6.522,28.874 L3.3@7.366,29.718
  Layer 2 w2: L3.3@7.5,29.852 7.691,29.661 9.339,29.661 14.85,24.15 15.35,24.15 Brd_CTS_pri.2@15.6,23.9
  Bottom Layer w2: L3.3@7.5,29.852 7.691,29.661 9.339,29.661 14.85,24.15 15.35,24.15 Brd_CTS_pri.2@15.6,23.9
  other v1: 14.293,22.295 14.969,22.295 15.645,22.295 16.321,22.295 16.997,22.295 14.267,25.577 14.943,25.577 15.619,25.577 16.296,25.577 16.972,25.577 8.875,28.92 9.339,29.852 9.163,30.689 6.664,31.227
CT2_P: Brd_CTS_pri.1 TRAN4.2 | length 30.9
  Top Layer w2: Brd_CTS_pri.1@20.1,23.9 20.829,23.171 27.129,23.171 TRAN4.2@27.4,22.9
  Layer 2 w2: Brd_CTS_pri.1@20.1,23.9 Brd_CTS_pri.1@20.35,23.65 ; TRAN4.2@23.717,23.028 24.467,22.278 TRAN4.2@27.258,22.278
  Layer 2 w3: Brd_CTS_pri.1@20.35,23.35 21.431,23.35 TRAN4.2@23.859,23.35
  Layer 3 w2: Brd_CTS_pri.1@20.1,23.9 Brd_CTS_pri.1@20.35,23.65 ; TRAN4.2@23.717,23.028 24.467,22.278 TRAN4.2@27.258,22.278
  Layer 3 w3: Brd_CTS_pri.1@20.35,23.35 21.431,23.35 TRAN4.2@23.859,23.35
  Bottom Layer w2: Brd_CTS_pri.1@20.1,23.9 20.35,23.65 23.859,23.65 24.609,22.9 TRAN4.2@27.4,22.9
  other v1: 24.608,20.667 25.284,20.667 25.96,20.667 26.636,20.667 27.312,20.667 27.988,20.667 28.665,20.667 29.341,20.667 30.017,20.667 18.726,22.295 19.402,22.295 20.078,22.295 20.755,22.295 21.431,22.295 24.5,23.889 25.176,23.889 25.852,23.889 26.528,23.889 27.205,23.889 27.881,23.889 28.557,23.889 29.233,23.889 29.909,23.889 18.846,25.577 19.522,25.577 20.198,25.577 20.874,25.577 21.55,25.577
GaN1_12V_H: J2.7 J8.20 | length 62.5
  Layer 2 w0.3: v3(24.305,7.991) 25.839,6.457 25.839,3.296 26.63,2.505 J8.20@26.63,1.2
  Layer 3 w0.254: v3(5.4,42.982) 5.448,42.935 5.448,42.001 5.597,41.852 7.603,41.852 10.271,39.185 10.271,20.734 8.227,18.691 8.227,10.419 9.01,9.636 11.841,9.636 12.21,9.267 13.797,7.68 14.522,6.955 23.269,6.955 v3(24.305,7.991)
  Bottom Layer w0.3: J8.20@26.486,1.344 J8.20@26.63,1.2
GaN1_INH: J2.6 J8.19 | length 63.8
  Layer 2 w0.254: v3(23.523,8.035) 23.523,7.966 23.643,7.846 23.643,7.772 25.359,6.056 J8.19@25.36,1.2
  Layer 3 w0.254: v3(7.234,46.871) 7.833,46.273 7.833,42.269 10.728,39.374 10.728,20.545 8.716,18.533 8.716,10.577 9.199,10.093 12.03,10.093 12.667,9.456 13.986,8.137 14.711,7.412 23.016,7.412 23.396,7.792 23.396,7.839 23.523,7.966 v3(23.523,8.035)
  Layer 3 w0.3: J8.19@25.25,1.31 J8.19@25.36,1.2
  Bottom Layer w0.3: J2.6@6.4,46.933 6.47,46.933 6.5,46.963 7.086,46.963 7.178,46.871 v3(7.234,46.871) ; J8.19@25.252,1.308 J8.19@25.36,1.2
GaN1_INL: J2.2 J8.12 | length 54
  Layer 2 w0.254: v3(21.09,42.126) 21.651,42.126 22.48,42.955 22.48,46.121 22.184,46.416 21.794,46.416 v3(21.761,46.382)
  Layer 2 w0.3: v3(15.149,9.82) 15.189,9.86 15.326,9.86 15.332,9.866 15.827,9.866 16.47,9.223 J8.12@16.47,1.2
  Layer 3 w0.254: v3(15.149,9.82) 15.143,9.815 14.753,9.815 14.321,10.247 14.321,10.731 14.442,10.851 14.442,16.428 12.533,18.337 12.533,31.732 15.746,34.945 17.003,34.945 18.728,36.67 18.728,38.704 21.154,41.13 21.154,41.883 21.139,41.898 21.139,42.078 v3(21.09,42.126)
  Bottom Layer w0.3: J2.2@21.2,46.333 21.249,46.382 v3(21.761,46.382)
GAN1_SW1_D: J2.8 J8.18 | length 66.3
  Layer 2 w0.254: v3(22.84,8.296) 22.889,8.247 22.889,7.843 24.749,5.982 24.749,3.002 24.189,2.441 24.189,1.299 J8.18@24.09,1.2
  Layer 3 w0.254: v3(5.4,48.069) 7.811,48.069 8.387,47.494 8.387,42.362 11.185,39.564 11.185,20.356 9.173,18.343 9.173,10.766 9.388,10.551 12.219,10.551 13.124,9.646 14.176,8.594 14.9,7.87 22.414,7.87 v3(22.84,8.296)
  Layer 3 w0.3: J8.18@24.053,1.237 J8.18@24.09,1.2
  Bottom Layer w0.5: J2.8@5.4,46.933 v3(5.4,48.069)
GaN2_12V_H: J3.7 J8.16 | length 21.1
  Layer 2 w0.3: v3(17.6,15.494) 16.069,15.494 15.677,15.102 15.677,15.101 15.11,14.534 15.11,12.271 15.666,11.714 17.505,11.714 19.409,9.81 19.409,4.987 21.55,2.846 21.55,2.068 J8.16@21.55,1.2
  Bottom Layer w0.3: J3.7@17.6,14.4 v3(17.6,15.494)
GaN2_INH: J3.6 J8.15 | length 12.5
  Layer 2 w0.3: v3(16.625,11.065) 17.443,11.065 18.906,9.602 18.906,4.744 20.28,3.37 J8.15@20.28,1.2
  Bottom Layer w0.254: J3.6@16.6,11.652 16.625,11.627 v3(16.625,11.065)
GaN2_INL: J3.2 J8.10 | length 22
  Layer 2 w0.2: v3(1.319,10.643) 1.631,10.955 2.902,10.955 3.556,10.301 3.556,9.923 5.031,8.448 5.031,3.903 6.088,2.846 13.384,2.846 13.93,2.3 J8.10@13.93,1.2
  Bottom Layer w0.3: v3(1.319,10.643) 1.375,10.643 1.533,10.8 1.7,10.8 1.802,10.902 J3.2@1.802,11.998
GaN2_SW: J3.SW TRAN4.1 | length 16.6
  Top Layer w2: TRAN4.1@26.81,13.406 TRAN4.1@27.192,13.789
  Layer 2 w3: J3.SW@20.1,13.2 20.85,13.2 23.873,13.2 24.416,13.743 25.084,14.411 TRAN4.1@27.334,14.411
  Layer 3 w3: J3.SW@20.1,13.2 20.85,13.2 23.873,13.2 24.416,13.743 25.084,14.411 TRAN4.1@27.334,14.411
  Bottom Layer w2: TRAN4.1@26.81,13.406 TRAN4.1@27.192,13.789
  other v1: 19.428,11.678 20.104,11.678 20.78,11.678 21.456,11.678 24.541,12.178 25.218,12.178 25.894,12.178 26.57,12.178 27.246,12.178 27.922,12.178 28.598,12.178 29.275,12.178 29.951,12.178 18.726,14.53 19.402,14.53 20.078,14.53 20.755,14.53 21.431,14.53 24.434,15.4 25.11,15.4 25.786,15.4 26.462,15.4 27.139,15.4 27.815,15.4 28.491,15.4 29.167,15.4 29.843,15.4
GaN2_SW_D: J3.8 J8.14 | length 11.5
  Layer 2 w0.3: v3(17.451,10.198) 18.373,9.276 18.373,4.794 18.403,4.764 18.403,4.536 19.01,3.928 J8.14@19.01,1.2
  Bottom Layer w0.3: v3(17.451,10.198) 17.451,10.254 17.535,10.338 17.535,10.8 17.6,10.865 J3.8@17.6,12
HVBUS: C69.1 C70.1 C71.1 C72.1 C138.1 C139.1 C140.1 C141.1 C142.1 C147.1 C148.1 C149.1 C150.1 C151.1 C168.1 C169.1 J2.HV J3.HV J8.1 pad.5@2.276,19.11 pad.5@11.206,45.654 R120.2 | length 23.9
  Layer 2 w0.2: v1(1.477,17.682) 0.368,16.574 0.368,3.332 J8.1@2.5,1.2
  Layer 2 w0.5: J3.HV@10.05,11.634 v1(10.186,11.769)
  Bottom Layer w0.5: J2.HV@11.5,45.133 12.774,43.859 C69.1@12.774,41.977 ; C148.1@34.173,24.67 34.346,24.67 34.825,24.192 34.825,23.035 R120.2@34.948,22.911
  other v1: 10.862,11.769 11.538,11.769 12.214,11.769 12.89,11.769 10.16,14.621 10.836,14.621 11.512,14.621 12.188,14.621 12.864,14.621 0.884,18.221 3.446,18.221 0.726,19.11 3.776,19.11 0.833,19.999 3.44,19.999 35.489,24.343 36.165,24.343 38.515,24.343 39.191,24.343 41.753,24.343 42.429,24.343 35.489,25.019 36.165,25.019 38.515,25.019 39.191,25.019 41.753,25.019 42.429,25.019 34.948,39.186 35.625,39.186 37.974,39.186 38.65,39.186 41.213,39.186 41.889,39.186 34.948,39.862 35.625,39.862 37.974,39.862 38.65,39.862 41.213,39.862 41.889,39.862 10.104,43.905 10.78,43.905 11.457,43.905 12.133,43.905 12.809,43.905 10.16,46.555 10.836,46.555 11.512,46.555 12.188,46.555 12.864,46.555
NetC147_2: C147.2 C148.2 C149.2 C150.2 C152.1 C153.1 C154.1 C155.1 L3.4
  other v1: 15.971,28.24 15.019,28.26 14.248,28.617 16.968,28.731 33.909,28.759 34.585,28.759 37.192,28.759 37.868,28.759 40.218,28.759 40.894,28.759 43.616,28.759 44.292,28.759 33.909,29.435 34.585,29.435 37.192,29.435 37.868,29.435 40.218,29.435 40.894,29.435 43.616,29.435 44.292,29.435 17.191,29.843 14.126,30.817 16.943,30.963 14.873,31.378 16.034,31.418
NetR51_1: R51.1 R53.2 U22.4 | length 4.1
  Bottom Layer w0.3: U22.4@44.831,5.349 44.831,5.429 44.956,5.554 45.308,5.554 45.834,6.08 45.834,6.1 46.11,6.376 46.256,6.376 R51.1@46.581,6.701 R53.2@48.278,6.701
NetR51_2: R51.2 U21.6 | length 6.3
  Bottom Layer w0.3: v3(41.57,2.966) 41.55,2.986 41.55,4.162 U21.6@41.529,4.182 41.607,4.261 41.607,5.311 41.89,5.593 43.098,5.593 44.205,6.701 R51.2@44.981,6.701
NetR103_2: R103.2 R104.1 U18.4 | length 3.4
  Bottom Layer w0.3: R103.2@29.759,7.576 31.038,7.576 R104.1@31.073,7.541 31.173,7.541 31.323,7.391 31.323,7.291 32.015,6.598 32.015,6.374 32.165,6.224 U18.4@32.415,6.224
NetR120_1: R120.1 R122.2 | length 2.3
  Bottom Layer w0.3: R120.1@34.948,20.011 36.943,20.011 R122.2@37.173,20.241
NetR122_1: R122.1 R123.2 | length 2.1
  Bottom Layer w0.3: R122.1@40.073,20.241 R123.2@42.166,20.241
NetR123_1: R123.1 R124.2 U21.2 | length 9
  Bottom Layer w0.3: U21.2@40.259,15.082 40.409,15.232 40.409,16.122 40.797,16.51 43.307,16.51 44.692,17.895 45.155,17.895 R124.2@45.429,18.17 ; R123.1@45.066,20.241 45.451,19.856 R124.2@45.451,18.355
NetU21_7: U21.7 U22.3 | length 6.1
  Bottom Layer w0.3: U21.7@40.409,3.697 40.409,3.123 41.691,1.841 44.097,1.841 44.706,2.451 44.706,2.674 U22.3@44.831,2.799
PB_3V3-s: C159.1 C171.1 pad.5@46.64,1.2 U21.8 U22.5 | length 15.9
  Top Layer w0.3: pad.5@46.64,1.2 46.64,4.066 v3(47.468,4.894)
  Bottom Layer w0.3: U22.5@46.731,5.349 46.731,5.224 46.856,5.099 46.981,5.099 47.206,4.874 47.468,4.874 C171.1@48.387,4.874
  Bottom Layer w0.5: U21.8@39.039,4.132 39.039,3.104 39.701,2.441 C159.1@39.701,1.501 39.926,1.276 40.169,1.276 40.244,1.2 pad.5@46.64,1.2
PB_AC_OK: J8.5
PB_AGND-s: C159.2 C171.2 pad.5@49.18,1.2 U21.5 U22.2 | length 18.2
  Layer 3 w0.3: v3(38.101,2.615) 38.427,2.29 43,2.29 43.616,2.906 v3(43.616,3.816) 44.088,3.816 v3(45.781,2.123) 47.242,3.584 47.448,3.584 v3(47.488,3.624)
  Bottom Layer w0.3: C159.2@38.101,1.501 v3(38.101,2.615) ; U21.5@42.741,4.24 U21.5@42.799,4.182 ; U21.5@42.799,3.758 42.857,3.816 v3(43.616,3.816) ; v3(45.781,2.123) U22.2@45.781,2.799 ; v3(47.488,3.624) 47.545,3.624 47.59,3.579 48.082,3.579 48.629,3.031 48.629,2.505 49.168,1.966 49.168,1.213 pad.5@49.18,1.2
PB_DGNDp: J8.4 R601.2 | length 1.7
  Bottom Layer w0.254: J8.4@6.31,1.2 6.31,2.733 R601.2@6.424,2.846
PB_GND_D: J2.4 J3.4 J8.9 | length 77.4
  Top Layer w0.3: J8.9@12.66,1.2 12.804,1.344 12.804,1.799 13.395,2.391 v3(17.098,2.391)
  Layer 2 w0.2: v3(2.808,10.261) 3.153,9.916 3.153,9.756 4.628,8.281 4.628,3.736 5.974,2.391 12.214,2.391 12.66,1.944 J8.9@12.66,1.2
  Layer 2 w0.254: v3(14.905,10.489) 14.928,10.512 15.861,10.512 16.95,9.422 16.95,2.608 17.098,2.459 v3(17.098,2.391)
  Layer 3 w0.254: v3(14.905,10.489) 14.899,10.495 14.899,16.618 12.99,18.526 12.99,31.543 15.935,34.488 17.192,34.488 19.185,36.48 19.185,38.514 21.611,40.94 21.611,41.725 22.48,42.594 22.48,46.714 22.228,46.967 20.469,46.967 20.421,47.014 v3@20.266,47.014
  Bottom Layer w0.254: J3.4@2.8,12 2.753,11.953 2.753,11.003 2.804,10.953 2.804,10.265 v3(2.808,10.261) ; J8.9@12.647,1.213 J8.9@12.66,1.2 ; v3(20.193,47.063) J2.4@20.197,47.059 ; J2.4@20.197,46.337 J2.4@20.2,46.333
PB_PFC_OK: J8.6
